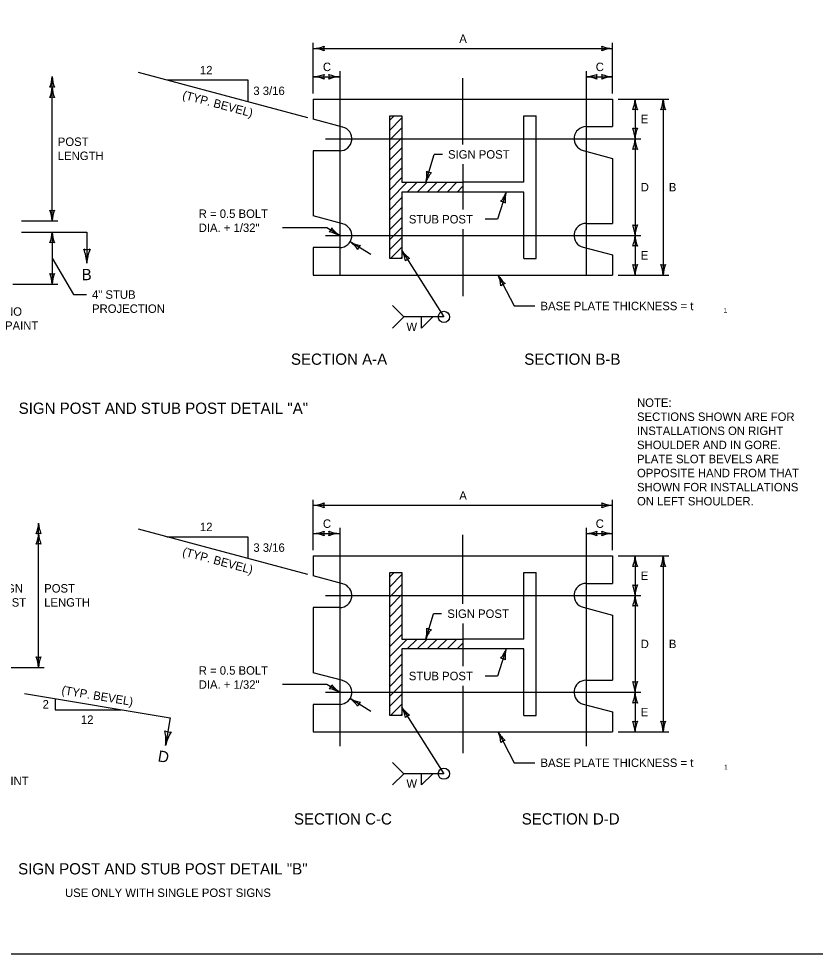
# Model space of a CAD drawing. Extents: x 49991.4 to 50021, y 49987.6 to 50011.4.
# Drawn here: x 50002.29 to 50007.94, y 49987.8 to 49994.44 of the extents above; entities that cross this region are included whole.
import ezdxf

# ---------------------------------------------------------------- set-up
doc = ezdxf.new("R2010")
doc.units = 0
for name, color, linetype in [('Level 1', 7, 'Continuous'), ('Level 2', 7, 'Continuous'), ('Level 3', 7, 'Continuous'), ('Level 5', 7, 'Continuous'), ('Level 6', 7, 'Continuous')]:
    doc.layers.add(name, color=color, linetype=linetype)

msp = doc.modelspace()

# ---------------------------------------------------------------- linework, layer by layer
at = {"layer": 'Level 1'}
for p, q in [((50004.3792, 49993.8723), (50006.5042, 49993.8723)), ((50004.3792, 49993.8723), (50004.3792, 49993.7302)), ((50006.5042, 49993.8723), (50006.5042, 49993.677)), ((50004.9217, 49992.7398), (50004.9217, 49993.7548)), ((50004.9217, 49993.7548), (50005.0079, 49993.7548)), ((50004.9217, 49993.7238), (50004.9527, 49993.7548)), ((50004.9217, 49993.6531), (50005.0079, 49993.7393)), ((50005.0079, 49993.7548), (50005.0079, 49993.2823)), ((50005.8754, 49993.7548), (50005.9617, 49993.7548)), ((50005.8754, 49993.2823), (50005.8754, 49993.7548)), ((50005.9617, 49992.7398), (50005.9617, 49993.7548)), ((50004.5889, 49993.6741), (50004.3792, 49993.7302)), ((50004.9217, 49993.5824), (50005.0079, 49993.6686)), ((50006.3167, 49993.677), (50006.5042, 49993.677)), ((50004.9217, 49993.5117), (50005.0079, 49993.5979)), ((50004.5667, 49993.5051), (50004.3792, 49993.5051)), ((50004.3792, 49993.5051), (50004.3792, 49993.0427)), ((50004.9217, 49993.4409), (50005.0079, 49993.5271)), ((50006.2945, 49993.508), (50006.5042, 49993.452)), ((50004.9217, 49993.3702), (50005.0079, 49993.4564)), ((50006.5042, 49993.452), (50006.5042, 49992.9895)), ((50004.9217, 49993.2995), (50005.0079, 49993.3857)), ((50004.9217, 49993.2288), (50005.0079, 49993.315)), ((50004.9217, 49993.1581), (50005.0459, 49993.2823)), ((50005.0079, 49993.2823), (50005.4417, 49993.2823)), ((50005.0466, 49993.2123), (50005.1166, 49993.2823)), ((50005.1173, 49993.2123), (50005.1873, 49993.2823)), ((50005.188, 49993.2123), (50005.258, 49993.2823)), ((50005.2587, 49993.2123), (50005.3287, 49993.2823)), ((50005.3295, 49993.2123), (50005.3995, 49993.2823)), ((50005.8754, 49993.2823), (50005.4417, 49993.2823)), ((50005.4417, 49993.2823), (50005.4417, 49993.2123)), ((50005.4417, 49993.2123), (50005.0079, 49993.2123)), ((50005.0079, 49993.2123), (50005.0079, 49992.7398)), ((50005.4002, 49993.2123), (50005.4417, 49993.2538)), ((50005.8754, 49993.2123), (50005.4417, 49993.2123)), ((50005.8754, 49992.7398), (50005.8754, 49993.2123)), ((50004.9217, 49993.0874), (50005.0079, 49993.1736)), ((50004.9217, 49993.0167), (50005.0079, 49993.1029)), ((50004.5889, 49992.9866), (50004.3792, 49993.0427)), ((50004.9217, 49992.946), (50005.0079, 49993.0322)), ((50004.9217, 49992.8753), (50005.0079, 49992.9615)), ((50006.3167, 49992.9895), (50006.5042, 49992.9895)), ((50004.9217, 49992.8045), (50005.0079, 49992.8907)), ((50004.5667, 49992.8176), (50004.3792, 49992.8176)), ((50004.3792, 49992.8176), (50004.3792, 49992.6223)), ((50004.9277, 49992.7398), (50005.0079, 49992.82)), ((50006.295, 49992.8204), (50006.5042, 49992.7658)), ((50005.0079, 49992.7398), (50004.9217, 49992.7398)), ((50004.9984, 49992.7398), (50005.0079, 49992.7493)), ((50005.8754, 49992.7398), (50005.9617, 49992.7398)), ((50006.5042, 49992.7658), (50006.5042, 49992.6223)), ((50004.3792, 49992.6223), (50006.5042, 49992.6223)), ((50004.3792, 49990.6281), (50006.5042, 49990.6281)), ((50004.3792, 49990.6281), (50004.3792, 49990.486)), ((50006.5042, 49990.6281), (50006.5042, 49990.4328)), ((50004.5889, 49990.4299), (50004.3792, 49990.486)), ((50004.9217, 49989.4956), (50004.9217, 49990.5106)), ((50004.9217, 49990.5106), (50005.0079, 49990.5106)), ((50004.9217, 49990.4796), (50004.9527, 49990.5106)), ((50004.9217, 49990.4089), (50005.0079, 49990.4951)), ((50005.0079, 49990.5106), (50005.0079, 49990.0381)), ((50005.8754, 49990.5106), (50005.9617, 49990.5106)), ((50005.8754, 49990.0381), (50005.8754, 49990.5106)), ((50005.9617, 49989.4956), (50005.9617, 49990.5106)), ((50004.9217, 49990.3382), (50005.0079, 49990.4244)), ((50006.3167, 49990.4328), (50006.5042, 49990.4328)), ((50004.9217, 49990.2675), (50005.0079, 49990.3537)), ((50004.9217, 49990.1967), (50005.0079, 49990.2829)), ((50004.5667, 49990.2609), (50004.3792, 49990.2609)), ((50004.3792, 49990.2609), (50004.3792, 49989.7985)), ((50004.9217, 49990.126), (50005.0079, 49990.2122)), ((50006.2945, 49990.2638), (50006.5042, 49990.2078)), ((50006.5042, 49990.2078), (50006.5042, 49989.7453)), ((50004.9217, 49990.0553), (50005.0079, 49990.1415)), ((50004.9217, 49989.9846), (50005.0079, 49990.0708)), ((50004.9217, 49989.9139), (50005.0459, 49990.0381)), ((50005.0079, 49990.0381), (50005.4417, 49990.0381)), ((50005.0466, 49989.9681), (50005.1166, 49990.0381)), ((50005.1173, 49989.9681), (50005.1873, 49990.0381)), ((50005.188, 49989.9681), (50005.258, 49990.0381)), ((50005.2587, 49989.9681), (50005.3287, 49990.0381)), ((50005.3295, 49989.9681), (50005.3995, 49990.0381)), ((50005.8754, 49990.0381), (50005.4417, 49990.0381)), ((50005.4417, 49990.0381), (50005.4417, 49989.9681)), ((50005.4417, 49989.9681), (50005.0079, 49989.9681)), ((50005.0079, 49989.9681), (50005.0079, 49989.4956)), ((50005.4002, 49989.9681), (50005.4417, 49990.0096)), ((50005.8754, 49989.9681), (50005.4417, 49989.9681)), ((50005.8754, 49989.4956), (50005.8754, 49989.9681)), ((50004.9217, 49989.8432), (50005.0079, 49989.9294)), ((50004.9217, 49989.7725), (50005.0079, 49989.8587)), ((50004.5889, 49989.7424), (50004.3792, 49989.7985)), ((50004.9217, 49989.7018), (50005.0079, 49989.788)), ((50004.9217, 49989.6311), (50005.0079, 49989.7173)), ((50006.3167, 49989.7453), (50006.5042, 49989.7453)), ((50004.9217, 49989.5603), (50005.0079, 49989.6465)), ((50004.5667, 49989.5734), (50004.3792, 49989.5734)), ((50004.3792, 49989.5734), (50004.3792, 49989.3781)), ((50004.9277, 49989.4956), (50005.0079, 49989.5758)), ((50006.295, 49989.5762), (50006.5042, 49989.5216)), ((50005.0079, 49989.4956), (50004.9217, 49989.4956)), ((50004.9984, 49989.4956), (50005.0079, 49989.5051)), ((50005.8754, 49989.4956), (50005.9617, 49989.4956)), ((50006.5042, 49989.5216), (50006.5042, 49989.3781)), ((50004.3792, 49989.3781), (50006.5042, 49989.3781))]:
    msp.add_line(p, q, dxfattribs=at)
msp.add_lwpolyline([(49999.3835, 49998.9992), (50016.7501, 49998.9992), (50016.7501, 49987.7988), (49999.3835, 49987.7988)], close=True, dxfattribs=at)
for centre, start, end in [((50004.5667, 49993.5911), 270, 75.82227), ((50006.3167, 49993.5911), 90, 255.82227), ((50004.5667, 49992.9036), 270, 75.82227), ((50006.3167, 49992.9036), 90, 256.44074), ((50004.5667, 49990.3469), 270, 75.82227), ((50006.3167, 49990.3469), 90, 255.82227), ((50004.5667, 49989.6594), 270, 75.82227), ((50006.3167, 49989.6594), 90, 256.44074)]:
    msp.add_arc(centre, 0.0859, start, end, dxfattribs=at)
at = {"layer": 'Level 3'}
for p, q in [((50004.3792, 49993.9123), (50004.3792, 49994.2717)), ((50006.5042, 49993.9123), (50006.5042, 49994.2717)), ((50004.3792, 49994.2317), (50006.5042, 49994.2317)), ((50002.5249, 49993.0073), (50002.5249, 49994.0327)), ((50004.3406, 49993.7406), (50003.1389, 49994.0619)), ((50003.3387, 49994.0085), (50003.9135, 49994.0085)), ((50003.9135, 49994.0085), (50003.9135, 49993.8548)), ((50004.3792, 49994.0317), (50004.5667, 49994.0317)), ((50005.4417, 49993.5498), (50005.4417, 49994.0223)), ((50006.3167, 49994.0317), (50006.5042, 49994.0317)), ((50006.5442, 49993.8723), (50006.9042, 49993.8723)), ((50006.6642, 49993.8723), (50006.6642, 49993.5911)), ((50006.8642, 49993.8723), (50006.8642, 49992.6223)), ((50006.6642, 49993.5911), (50006.6642, 49992.9036)), ((50005.1791, 49993.2823), (50005.2374, 49993.4798)), ((50005.2961, 49993.4798), (50005.2374, 49993.4798)), ((50005.4417, 49993.4098), (50005.4417, 49993.0895)), ((50005.7497, 49993.2123), (50005.687, 49993.0195)), ((50002.307, 49993.0073), (50002.5649, 49993.0073)), ((50005.687, 49993.0195), (50005.5994, 49993.0195)), ((50004.4762, 49992.9589), (50004.1604, 49992.9589)), ((50004.5667, 49992.9036), (50004.4762, 49992.9589)), ((50005.4417, 49992.9495), (50005.4417, 49992.4723)), ((50002.5249, 49992.928), (50002.5249, 49992.5575)), ((50006.6642, 49992.9036), (50006.6642, 49992.6223)), ((50004.7881, 49992.7685), (50004.64, 49992.8588)), ((50002.5249, 49992.7428), (50002.6772, 49992.4845)), ((50005.0079, 49992.7969), (50005.3071, 49992.3257)), ((50005.6923, 49992.6223), (50005.805, 49992.4034)), ((50006.5442, 49992.6223), (50006.9042, 49992.6223)), ((50002.2446, 49992.5575), (50002.5649, 49992.5575)), ((50002.6772, 49992.4845), (50002.7679, 49992.4845)), ((50004.9427, 49992.4057), (50005.0227, 49992.3257)), ((50005.805, 49992.4034), (50005.9527, 49992.4034)), ((50004.9427, 49992.2457), (50005.0227, 49992.3257)), ((50005.3071, 49992.3257), (50005.0227, 49992.3257)), ((50005.1471, 49992.2457), (50005.1471, 49992.3257)), ((50005.1471, 49992.2457), (50005.2271, 49992.3257)), ((50005.1472, 49992.3256), (50005.1472, 49992.3256)), ((50004.3792, 49990.6681), (50004.3792, 49991.0275)), ((50006.5042, 49990.6681), (50006.5042, 49991.0275)), ((50004.3792, 49990.9875), (50006.5042, 49990.9875)), ((50002.4283, 49989.8352), (50002.4283, 49990.8606)), ((50004.3406, 49990.4964), (50003.1389, 49990.8177)), ((50003.3387, 49990.7643), (50003.9135, 49990.7643)), ((50003.9135, 49990.7643), (50003.9135, 49990.6106)), ((50004.3792, 49990.7875), (50004.5667, 49990.7875)), ((50005.4417, 49990.2877), (50005.4417, 49990.7781)), ((50006.3167, 49990.7875), (50006.5042, 49990.7875)), ((50006.5442, 49990.6281), (50006.9042, 49990.6281)), ((50006.6642, 49990.6281), (50006.6642, 49990.3469)), ((50006.8642, 49990.6281), (50006.8642, 49989.3781)), ((50006.6642, 49990.3469), (50006.6642, 49989.6594)), ((50005.1791, 49990.0381), (50005.2321, 49990.2177)), ((50005.2908, 49990.2177), (50005.2321, 49990.2177)), ((50005.4417, 49990.1477), (50005.4417, 49989.8453)), ((50005.7497, 49989.9681), (50005.687, 49989.7753)), ((50001.7296, 49989.8352), (50002.4683, 49989.8352)), ((50005.687, 49989.7753), (50005.5994, 49989.7753)), ((50004.4762, 49989.7147), (50004.1604, 49989.7147)), ((50004.5667, 49989.6594), (50004.4762, 49989.7147)), ((50005.4417, 49989.7053), (50005.4417, 49989.2281)), ((50002.5472, 49989.6135), (50002.5472, 49989.5355)), ((50004.788, 49989.5242), (50004.64, 49989.6146)), ((50006.6642, 49989.6594), (50006.6642, 49989.3781)), ((50005.0079, 49989.5527), (50005.3071, 49989.0815)), ((50002.5472, 49989.5355), (50003.0153, 49989.5355)), ((50005.6923, 49989.3781), (50005.805, 49989.1592)), ((50006.5442, 49989.3781), (50006.9042, 49989.3781)), ((50004.9427, 49989.1615), (50005.0227, 49989.0815)), ((50005.805, 49989.1592), (50005.9527, 49989.1592)), ((50004.9427, 49989.0015), (50005.0227, 49989.0815)), ((50005.3071, 49989.0815), (50005.0227, 49989.0815)), ((50005.1471, 49989.0015), (50005.1471, 49989.0815)), ((50005.1471, 49989.0015), (50005.2271, 49989.0815))]:
    msp.add_line(p, q, dxfattribs=at)
for centre in [(50005.3071, 49992.3257), (50005.3071, 49989.0815)]:
    msp.add_circle(centre, 0.04, dxfattribs=at)
for centre, radius, start, end in [((50004.3677, 49994.4644), 0.233, 272.82731, 292.07716), ((50004.37, 49994.0096), 0.2223, 67.45601, 87.63952), ((50004.5074, 49994.2317), 0.0548, 162.13882, 197.86118), ((50006.5134, 49994.4538), 0.2223, 247.45601, 267.63952), ((50006.376, 49994.2317), 0.0548, 342.13882, 17.86118), ((50006.5157, 49993.999), 0.233, 92.82731, 112.07716), ((50002.3028, 49994.0419), 0.2223, 337.45601, 357.63952), ((50002.7576, 49994.0442), 0.233, 182.82731, 202.07716), ((50004.3677, 49994.2644), 0.233, 272.82731, 292.07716), ((50004.37, 49993.8096), 0.2223, 67.45601, 87.63952), ((50004.5074, 49994.0317), 0.0548, 162.13882, 197.86118), ((50004.5759, 49994.2538), 0.2223, 247.45601, 267.63952), ((50004.4385, 49994.0317), 0.0548, 342.13882, 17.86118), ((50004.5782, 49993.799), 0.233, 92.82731, 112.07716), ((50006.3052, 49994.2644), 0.233, 272.82731, 292.07716), ((50006.3075, 49993.8096), 0.2223, 67.45601, 87.63952), ((50006.4449, 49994.0317), 0.0548, 162.13882, 197.86118), ((50006.5134, 49994.2538), 0.2223, 247.45601, 267.63952), ((50006.376, 49994.0317), 0.0548, 342.13882, 17.86118), ((50006.5157, 49993.799), 0.233, 92.82731, 112.07716), ((50002.3028, 49993.9684), 0.2223, 337.45601, 357.63952), ((50002.5249, 49993.9045), 0.0548, 72.13882, 107.86118), ((50002.7576, 49993.9708), 0.233, 182.82731, 202.07716), ((50002.5249, 49993.831), 0.0548, 72.13882, 107.86118), ((50006.4421, 49993.8815), 0.2223, 337.45601, 357.63952), ((50006.8969, 49993.8838), 0.233, 182.82731, 202.07716), ((50006.6421, 49993.8815), 0.2223, 337.45601, 357.63952), ((50007.0969, 49993.8838), 0.233, 182.82731, 202.07716), ((50006.6642, 49993.7441), 0.0548, 72.13882, 107.86118), ((50006.8642, 49993.7441), 0.0548, 72.13882, 107.86118), ((50006.6642, 49993.7193), 0.0548, 252.13882, 287.86118), ((50006.4315, 49993.5796), 0.233, 2.82731, 22.07716), ((50006.8863, 49993.5819), 0.2223, 157.45601, 177.63952), ((50006.4421, 49993.6003), 0.2223, 337.45601, 357.63952), ((50006.8969, 49993.6026), 0.233, 182.82731, 202.07716), ((50006.6642, 49993.4629), 0.0548, 72.13882, 107.86118), ((50004.9527, 49993.3372), 0.233, 346.37226, 5.62211), ((50005.3895, 49993.2106), 0.2223, 141.00096, 161.18447), ((50005.2154, 49993.4053), 0.0548, 235.68377, 271.40613), ((50005.5412, 49993.2897), 0.2223, 319.44905, 339.63256), ((50005.9745, 49993.1513), 0.233, 164.82035, 184.0702), ((50005.71, 49993.0904), 0.0548, 54.13186, 89.85422), ((50002.5249, 49993.1355), 0.0548, 252.13882, 287.86118), ((50002.2922, 49992.9958), 0.233, 2.82731, 22.07716), ((50002.747, 49992.9981), 0.2223, 157.45601, 177.63952), ((50004.4573, 49992.9705), 0.0548, 310.71181, 346.43418), ((50004.6903, 49993.0884), 0.2223, 216.02901, 236.21251), ((50006.6642, 49993.0318), 0.0548, 252.13882, 287.86118), ((50006.4315, 49992.8921), 0.233, 2.82731, 22.07716), ((50006.8863, 49992.8944), 0.2223, 157.45601, 177.63952), ((50002.3028, 49992.9372), 0.2223, 337.45601, 357.63952), ((50002.7576, 49992.9395), 0.233, 182.82731, 202.07716), ((50004.4552, 49992.699), 0.233, 61.40031, 80.65016), ((50006.4421, 49992.9128), 0.2223, 337.45601, 357.63952), ((50006.8969, 49992.9151), 0.233, 182.82731, 202.07716), ((50002.5249, 49992.7998), 0.0548, 72.13882, 107.86118), ((50004.5165, 49992.6739), 0.2223, 36.06348, 56.24699), ((50004.7514, 49993.0634), 0.233, 241.43478, 260.68463), ((50004.7495, 49992.792), 0.0548, 130.74629, 166.46865), ((50006.6642, 49992.7754), 0.0548, 72.13882, 107.86118), ((50004.8155, 49992.6855), 0.2223, 9.8716, 30.05511), ((50005.1982, 49992.9313), 0.233, 215.2429, 234.49275), ((50005.0766, 49992.6886), 0.0548, 104.55441, 140.27677), ((50006.6642, 49992.7505), 0.0548, 252.13882, 287.86118), ((50006.4315, 49992.6108), 0.233, 2.82731, 22.07716), ((50006.8863, 49992.6131), 0.2223, 157.45601, 177.63952), ((50006.8642, 49992.7505), 0.0548, 252.13882, 287.86118), ((50006.6315, 49992.6108), 0.233, 2.82731, 22.07716), ((50007.0863, 49992.6131), 0.2223, 157.45601, 177.63952), ((50002.5249, 49992.6857), 0.0548, 252.13882, 287.86118), ((50002.2922, 49992.546), 0.233, 2.82731, 22.07716), ((50002.747, 49992.5483), 0.2223, 157.45601, 177.63952), ((50005.4906, 49992.5288), 0.2223, 4.69755, 24.88106), ((50005.8939, 49992.739), 0.233, 210.06885, 229.3187), ((50005.751, 49992.5083), 0.0548, 99.38036, 135.10272), ((50004.3677, 49991.2202), 0.233, 272.82731, 292.07716), ((50004.37, 49990.7654), 0.2223, 67.45601, 87.63952), ((50004.5074, 49990.9875), 0.0548, 162.13882, 197.86118), ((50006.5134, 49991.2096), 0.2223, 247.45601, 267.63952), ((50006.376, 49990.9875), 0.0548, 342.13882, 17.86118), ((50006.5157, 49990.7548), 0.233, 92.82731, 112.07716), ((50002.2062, 49990.8698), 0.2223, 337.45601, 357.63952), ((50002.661, 49990.8721), 0.233, 182.82731, 202.07716), ((50002.2062, 49990.7963), 0.2223, 337.45601, 357.63952), ((50002.4283, 49990.7324), 0.0548, 72.13882, 107.86118), ((50002.661, 49990.7987), 0.233, 182.82731, 202.07716), ((50004.3677, 49991.0202), 0.233, 272.82731, 292.07716), ((50004.37, 49990.5654), 0.2223, 67.45601, 87.63952), ((50004.5074, 49990.7875), 0.0548, 162.13882, 197.86118), ((50004.5759, 49991.0096), 0.2223, 247.45601, 267.63952), ((50004.4385, 49990.7875), 0.0548, 342.13882, 17.86118), ((50004.5782, 49990.5548), 0.233, 92.82731, 112.07716), ((50006.3052, 49991.0202), 0.233, 272.82731, 292.07716), ((50006.3075, 49990.5654), 0.2223, 67.45601, 87.63952), ((50006.4449, 49990.7875), 0.0548, 162.13882, 197.86118), ((50006.5134, 49991.0096), 0.2223, 247.45601, 267.63952), ((50006.376, 49990.7875), 0.0548, 342.13882, 17.86118), ((50006.5157, 49990.5548), 0.233, 92.82731, 112.07716), ((50002.4283, 49990.6589), 0.0548, 72.13882, 107.86118), ((50006.4421, 49990.6373), 0.2223, 337.45601, 357.63952), ((50006.8969, 49990.6396), 0.233, 182.82731, 202.07716), ((50006.6421, 49990.6373), 0.2223, 337.45601, 357.63952), ((50007.0969, 49990.6396), 0.233, 182.82731, 202.07716), ((50006.6642, 49990.4999), 0.0548, 72.13882, 107.86118), ((50006.8642, 49990.4999), 0.0548, 72.13882, 107.86118), ((50006.6642, 49990.4751), 0.0548, 252.13882, 287.86118), ((50006.4315, 49990.3354), 0.233, 2.82731, 22.07716), ((50006.8863, 49990.3377), 0.2223, 157.45601, 177.63952), ((50006.4421, 49990.3561), 0.2223, 337.45601, 357.63952), ((50006.8969, 49990.3584), 0.233, 182.82731, 202.07716), ((50006.6642, 49990.2187), 0.0548, 72.13882, 107.86118), ((50004.9527, 49990.093), 0.233, 346.37226, 5.62211), ((50005.3895, 49989.9664), 0.2223, 141.00096, 161.18447), ((50005.2154, 49990.1611), 0.0548, 235.68377, 271.40613), ((50005.5412, 49990.0455), 0.2223, 319.44905, 339.63256), ((50005.9745, 49989.9071), 0.233, 164.82035, 184.0702), ((50002.4283, 49989.9634), 0.0548, 252.13882, 287.86118), ((50002.1956, 49989.8237), 0.233, 2.82731, 22.07716), ((50002.6504, 49989.826), 0.2223, 157.45601, 177.63952), ((50005.71, 49989.8462), 0.0548, 54.13186, 89.85422), ((50004.4573, 49989.7263), 0.0548, 310.71181, 346.43418), ((50004.4552, 49989.4548), 0.233, 61.40031, 80.65016), ((50004.6903, 49989.8442), 0.2223, 216.02901, 236.21251), ((50006.6642, 49989.7876), 0.0548, 252.13882, 287.86118), ((50006.4315, 49989.6479), 0.233, 2.82731, 22.07716), ((50006.8863, 49989.6502), 0.2223, 157.45601, 177.63952), ((50004.5165, 49989.4297), 0.2223, 36.06348, 56.24699), ((50004.7514, 49989.8192), 0.233, 241.43478, 260.68463), ((50006.4421, 49989.6686), 0.2223, 337.45601, 357.63952), ((50006.8969, 49989.6709), 0.233, 182.82731, 202.07716), ((50004.7495, 49989.5478), 0.0548, 130.74629, 166.46865), ((50004.8155, 49989.4413), 0.2223, 9.8716, 30.05511), ((50005.1982, 49989.6871), 0.233, 215.2429, 234.49275), ((50006.6642, 49989.5312), 0.0548, 72.13882, 107.86118), ((50005.0766, 49989.4444), 0.0548, 104.55441, 140.27677), ((50006.6642, 49989.5063), 0.0548, 252.13882, 287.86118), ((50006.4315, 49989.3666), 0.233, 2.82731, 22.07716), ((50006.8863, 49989.3689), 0.2223, 157.45601, 177.63952), ((50006.8642, 49989.5063), 0.0548, 252.13882, 287.86118), ((50006.6315, 49989.3666), 0.233, 2.82731, 22.07716), ((50007.0863, 49989.3689), 0.2223, 157.45601, 177.63952), ((50005.4906, 49989.2846), 0.2223, 4.69755, 24.88106), ((50005.8939, 49989.4948), 0.233, 210.06885, 229.3187), ((50005.751, 49989.2641), 0.0548, 99.38036, 135.10272)]:
    msp.add_arc(centre, radius, start, end, dxfattribs=at)
at = {"layer": 'Level 5'}
for p, q in [((50004.5667, 49994.0717), (50004.5667, 49992.6223)), ((50006.3167, 49994.0717), (50006.3167, 49992.6223)), ((50004.4667, 49993.5911), (50006.7042, 49993.5911)), ((50004.4667, 49992.9036), (50006.7042, 49992.9036)), ((50004.5667, 49990.8275), (50004.5667, 49989.2781)), ((50006.3167, 49990.8275), (50006.3167, 49989.2781)), ((50004.4667, 49990.3469), (50006.7042, 49990.3469)), ((50004.4667, 49989.6594), (50006.7042, 49989.6594))]:
    msp.add_line(p, q, dxfattribs=at)
at = {"layer": 'Level 6'}
for p, q in [((50002.307, 49992.928), (50002.7711, 49992.928)), ((50002.7711, 49992.928), (50002.7711, 49992.7066)), ((50002.3274, 49989.6502), (50003.3633, 49989.4775)), ((50003.3633, 49989.4775), (50003.3306, 49989.2813))]:
    msp.add_line(p, q, dxfattribs=at)
for centre, radius, start, end in [((50002.7711, 49992.8776), 0.073, 252.13882, 287.86118), ((50002.4608, 49992.6913), 0.3107, 2.82731, 22.07716), ((50003.0673, 49992.6944), 0.2964, 157.45601, 177.63952), ((50003.3587, 49989.4499), 0.073, 242.6765, 278.39886), ((50003.022, 49989.3172), 0.3107, 353.36499, 12.61484), ((50003.6207, 49989.2206), 0.2964, 147.99369, 168.1772)]:
    msp.add_arc(centre, radius, start, end, dxfattribs=at)

# ---------------------------------------------------------------- texts
at = {"layer": 'Level 2'}
for s, height, p in [('A', 0.06, (50005.416, 49994.2717)), ('C', 0.06, (50004.4474, 49994.0717)), ('C', 0.06, (50006.3849, 49994.0717)), ('12', 0.06, (50003.5741, 49994.0485)), ('3 3/16', 0.06, (50003.9535, 49993.9016)), ('E', 0.06, (50006.7042, 49993.7017)), ('POST', 0.06, (50002.5649, 49993.54)), ('LENGTH', 0.06, (50002.5649, 49993.44)), ('SIGN POST', 0.06, (50005.3361, 49993.4498)), ('D', 0.06, (50006.7042, 49993.2174)), ('B', 0.06, (50006.9042, 49993.2173)), ('R = 0.5 BOLT', 0.06, (50003.5653, 49993.0289)), ('STUB POST', 0.06, (50005.0577, 49992.9895)), ('DIA. + 1/32"', 0.06, (50003.5653, 49992.9289)), ('E', 0.06, (50006.7042, 49992.733)), ('B', 0.08, (50002.7341, 49992.5866)), ('4" STUB', 0.06, (50002.8079, 49992.4545)), ('PROJECTION', 0.06, (50002.8079, 49992.3545)), ('BASE PLATE THICKNESS = t', 0.06, (50005.9927, 49992.3734)), ('NO', 0.06, (50002.1901, 49992.334)), ('1', 0.0325, (50007.2935, 49992.3561)), ('PAINT', 0.06, (50002.1901, 49992.234)), ('W', 0.06, (50005.0406, 49992.2257)), ('SECTION A-A', 0.08, (50004.2205, 49991.9858)), ('SECTION B-B', 0.08, (50005.8773, 49991.9858)), ('NOTE:', 0.06, (50006.6781, 49991.6868)), ('SIGN POST AND STUB POST DETAIL "A"', 0.08, (50002.2869, 49991.6371)), ('SECTIONS SHOWN ARE FOR', 0.06, (50006.6781, 49991.5868)), ('INSTALLATIONS ON RIGHT', 0.06, (50006.6781, 49991.4868)), ('SHOULDER AND IN GORE.', 0.06, (50006.6781, 49991.3868)), ('PLATE SLOT BEVELS ARE', 0.06, (50006.6781, 49991.2868)), ('OPPOSITE HAND FROM THAT', 0.06, (50006.6781, 49991.1868)), ('SHOWN FOR INSTALLATIONS', 0.06, (50006.6781, 49991.0868)), ('A', 0.06, (50005.416, 49991.0275)), ('ON LEFT SHOULDER.', 0.06, (50006.6781, 49990.9868)), ('C', 0.06, (50004.4474, 49990.8275)), ('C', 0.06, (50006.3849, 49990.8275)), ('12', 0.06, (50003.5741, 49990.8043)), ('3 3/16', 0.06, (50003.9535, 49990.6574)), ('E', 0.06, (50006.7042, 49990.4575)), ('SIGN', 0.06, (50002.1214, 49990.3679)), ('POST', 0.06, (50002.4683, 49990.3679)), ('POST', 0.06, (50002.1214, 49990.2679)), ('LENGTH', 0.06, (50002.4683, 49990.2679)), ('SIGN POST', 0.06, (50005.3308, 49990.1877)), ('D', 0.06, (50006.7042, 49989.9732)), ('B', 0.06, (50006.9042, 49989.9731)), ('R = 0.5 BOLT', 0.06, (50003.5653, 49989.7847)), ('DIA. + 1/32"', 0.06, (50003.5653, 49989.6847)), ('STUB POST', 0.06, (50005.0577, 49989.7453)), ('2', 0.06, (50002.4569, 49989.5445)), ('E', 0.06, (50006.7042, 49989.4888)), ('12', 0.06, (50002.7291, 49989.4355)), ('BASE PLATE THICKNESS = t', 0.06, (50005.9927, 49989.1292)), ('1', 0.0325, (50007.2967, 49989.1119)), ('PAINT', 0.06, (50002.1214, 49989.0004)), ('W', 0.06, (50005.0406, 49988.9815)), ('SECTION C-C', 0.08, (50004.2418, 49988.7204)), ('SECTION D-D', 0.08, (50005.8593, 49988.7204)), ('SIGN POST AND STUB POST DETAIL "B"', 0.08, (50002.2831, 49988.3659)), ('USE ONLY WITH SINGLE POST SIGNS', 0.06, (50002.616, 49988.2059))]:
    msp.add_text(s, height=height, dxfattribs=at).set_placement(p)
for s, height, rotation, p in [('(TYP. BEVEL)', 0.06, 345.023, (50003.4455, 49993.8764)), ('(TYP. BEVEL)', 0.06, 345.023, (50003.4455, 49990.6322)), ('(TYP. BEVEL)', 0.059999, 350.539, (50002.5881, 49989.6472)), ('D', 0.08, 350.55, (50003.271, 49989.1696))]:
    msp.add_text(s, height=height, rotation=rotation, dxfattribs=at).set_placement(p)

doc.saveas('drawing.dxf')
